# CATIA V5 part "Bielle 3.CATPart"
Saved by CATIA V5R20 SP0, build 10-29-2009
Part number: Bielle 3
Bounding box of the stored display mesh (mm): x -45 to 70, y -115.127 to 15.012, z -164.935 to 200.088
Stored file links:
  D:\Dropbox\IAO_2011\MMS_GR1\0\video\IAO_2011_1503_rjugie\rjugie\IAO_2011_1503_rjugie\Bielle 3.CATPart
  D:\Dropbox\IAO_2011\MMS_GR1\0\video\IAO_2011_1503_rjugie\rjugie\IAO_2011_1503_rjugie\rjugie.CATProduct
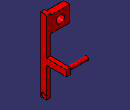
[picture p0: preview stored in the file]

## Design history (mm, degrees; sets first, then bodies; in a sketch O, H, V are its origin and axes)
External parameters (linked from other documents)
  External.Rayon_trou_bielle = 10 mm
  External.Epaisseur_bielle = 20 mm
  External.Hauteur_bielle = 15 mm
  External.hf = -100 mm
  External.vf = 150 mm
  External.vd = -150 mm
  External.Rayon_tige = 15 mm
Set1
  Plane1: linked copy from another document
  Point1 "A": linked copy from another document
  Point2 "F": linked copy from another document
  Point3 "D": linked copy from another document
  Plane2: linked copy from another document
  Line1: linked copy from another document
  Line2: linked copy from another document
Body1 (main body)
  Sketch1 on Plane1, origin (0, 0, 0), H (0, 1, 0), V (0, 0, 1)
    circle A1 centre (0, 0) radius 10
    point P1 (0, 0)
    reference projected point E1 (0, 0) from Point1
    radius A1 = 10 {= External.Rayon_trou_bielle}
    coincidence: E1 P1
  Pad1: profile Sketch1, direction (-1, 0, 0), length 45, opposite side length 50
  Sketch2 on Plane1, origin (0, 0, 0), H (0, 1, 0), V (0, 0, 1)
    line L1 (-114.8462, 200.0884) -> (-84.8462, 200.0653)
    line L2 (-84.8462, 200.0653) -> (-84.9884, 15.0654)
    line L3 (-84.9884, 15.0654) -> (15.0115, 14.9885)
    line L4 (15.0115, 14.9885) -> (14.9885, -15.0115)
    line L5 (14.9885, -15.0115) -> (-85.0115, -14.9346)
    point P6 (-85.0115, -14.9346)
    line L6 (-85.0115, -14.9346) -> (-85.1269, -164.9346)
    line L7 (-85.1269, -164.9346) -> (-115.1268, -164.9115)
    line L8 (-115.1268, -164.9115) -> (-114.8462, 200.0884)
    reference projected point E1 (0, 0) from Point1
    reference projected point E2 (0, 0) from Point1
    reference projected point E3 (-99.8846, 150.0769) from Point2
    reference projected point E4 (-99.8846, 150.0769) from Point2
    circle A1 centre (-100.1153, -149.9231) radius 10
    point P9 (-100.1153, -149.9231)
    reference projected point E5 (-100.1153, -149.9231) from Point3
    reference projected line E6 (-99.8847, 150) -> (-100.1154, -150) from Line1
    reference projected line E7 (-99.8847, 150) -> (-100.1154, -150) from Line1
    reference projected line E8 (-99.8847, 150) -> (-100.1154, -150) from Line1
    reference projected line E9 (-99.8847, 150) -> (-100.1154, -150) from Line1
    reference projected line E10 (-99.8847, 150) -> (-100.1154, -150) from Line1
    reference projected line E11 (-100, 0.0769) -> (0, 0) from Line2
    reference projected line E12 (-100, 0.0769) -> (0, 0) from Line2
    reference projected line E13 (-100, 0.0769) -> (0, 0) from Line2
    distance E1 L3 = 15 {= External.Hauteur_bielle}
    distance E2 L5 = 15 {= External.Hauteur_bielle}
    distance L2 E3 = 15 {= External.Hauteur_bielle}
    distance L8 E4 = 15 {= External.Hauteur_bielle}
    length L2 = 185 {= External.vf -External.Hauteur_bielle +50mm}
    length L5 = -100 {= External.hf}
    length L6 = 150 {= -External.vd}
    radius A1 = 10 {= External.Rayon_trou_bielle}
    coincidence: P6 L2, P9 E5
    parallelism: L8 E6, L2 E8, L6 E9, L5 E11, L3 E12
    perpendicularity: L1 E7, L7 E10, L4 E13
  Pad2: profile Sketch2, direction (1, 0, 0), length 50, opposite side length -70 {= -50mm-External.Epaisseur_bielle}
  Sketch3 on Plane2, origin (0, 0, 0), H (-1, 0, 0), V (0, 0.0008, 1)
    line L1 (45, 190) -> (-50, 190)
    line L2 (-50, 190) -> (-50, 110)
    line L3 (-50, 110) -> (45, 110)
    line L4 (45, 110) -> (45, 190)
    circle A1 centre (0, 150) radius 20
    point P5 (0, 150)
    distance L3 H = 110 {= External.vf -40mm}
    distance L4 V = 45
    distance L1 H = 190 {= External.vf +40mm}
    distance L2 V = 50
    distance P5 H = 150 {= External.vf}
    distance P5 V = 0
    radius A1 = 20 {= External.Rayon_tige +5mm}
    horizontal: L1 H, L3 H
    vertical: L2 V, L4 V
  Pad3: profile Sketch3, direction (0, 1, -0.0008), length -115 {= External.hf -External.Hauteur_bielle}, opposite side length 85 {= -External.hf -External.Hauteur_bielle}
